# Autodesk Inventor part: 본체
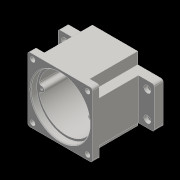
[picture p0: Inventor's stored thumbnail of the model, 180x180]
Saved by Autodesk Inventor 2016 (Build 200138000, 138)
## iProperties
Created: 2020-08
Part Number: 본체
Material: 일반
Document SubType Name: Modeling
Designer: User
Density: 1 g/cm^3
Appearance: 기본값
Author: User
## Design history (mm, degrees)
sketch "스케치1"
  geometry: L1 (47, 47)-(-47, 47); L2 (-47, 47)-(-47, -47); L3 (-47, -47)-(47, -47); L4 (47, -47)-(47, 47); L5 (47, 47)-(-47, -47); L6 (-47, 47)-(47, -47); 1 further point
  constraints: 12 end point, 2 midpoint, 2 parallel, 1 horizontal, 1 perpendicular
  dimensions: "d0" = 94 distance of L2.end L3.end; "d1" = 94 distance of L1.end L2.end
extrude "돌출1" new body sketch "스케치1" distance "d2" = 80; taper "d3" = 0 deg
sketch "스케치2"
  geometry: L1 (-70, -30)-(70, -30); L2 (70, -30)-(70, 30); L3 (70, 30)-(-70, 30); L4 (-70, 30)-(-70, -30); L5 (-70, -30)-(70, 30); L6 (70, -30)-(-70, 30); 1 further point
  constraints: 12 end point, 2 midpoint, 2 parallel, 1 horizontal, 1 perpendicular
  dimensions: "d4" = 60 distance of L1.end L2.end; "d5" = 140 distance of L2.end L3.end
extrude "돌출2" join sketch "스케치2" distance "d6" = 13; taper "d7" = 0 deg
sketch "스케치4"
  geometry: L1 (47, 47)-(-47, 47) reference; L2 (-47, 47)-(-33, 47); L3 (-33, 47)-(-33, 30); L4 (-33, 30)-(-47, 30); L5 (-47, 30)-(-47, 47); 1 further point
  constraints: 8 end point, 2 parallel, 1 horizontal, 1 perpendicular
  dimensions: "d8" = 17 distance of L2.end L3.end; "d9" = 14 distance of L3.end L4.end
extrude "돌출3" cut sketch "스케치4" distance "d10" = 70; taper "d11" = 0 deg
sketch "스케치5"
  geometry: L1 (-47, 47)-(-33, 47) reference; L2 (-47, 30)-(-47, 47) reference; C1 r 3.5 at (-40, 40); 1 further point
  constraints: 1 centre point
  dimensions: "d12" = 7 distance from line of L1 C1.centre; "d13" = 7 distance from line of C1.centre L2; "d14" = 7 diameter of C1
extrude "돌출4" cut sketch "스케치5" distance "d15" = 70; taper "d16" = 0 deg
sketch "스케치6"
  geometry: C1 r 27.5 at (0, 11); 1 further point
  constraints: 1 centre point, 1 vertical alignment
  dimensions: "d23" = 55 diameter of C1; "d24" = 11 distance of point (0, 0) C1.centre
extrude "돌출5" join sketch "스케치6" distance "d25" = 7; taper "d26" = 0 deg
sketch "스케치7"
  geometry: C1 r 27.5 at (0, 0) reference; C2 r 16 at (0, 0); 1 further point
  constraints: 1 centre point, 1 coincident
  dimensions: "d27" = 32 diameter of C2
extrude "돌출6" cut sketch "스케치7" distance "d28" = 8.3; taper "d29" = 0 deg
sketch "스케치8"
  geometry: C1 r 43 at (0, 0); 1 further point
  constraints: 1 centre point, 1 coincident
  dimensions: "d30" = 86 diameter of C1
extrude "돌출7" cut sketch "스케치8" distance "d31" = 9; taper "d32" = 0 deg
sketch "스케치9"
  geometry: C1 r 40 at (0, 0); 1 further point
  constraints: 1 centre point, 1 coincident
  dimensions: "d33" = 80 diameter of C1
extrude "돌출8" cut sketch "스케치9" distance "d34" = 62; taper "d35" = 0 deg
sketch "스케치10"
  geometry: C1 r 16 at (0, -11) reference; C2 r 21 at (0, -11); 1 further point
  constraints: 1 centre point, 1 coincident
  dimensions: "d36" = 42 diameter of C2
extrude "돌출9" join sketch "스케치10" distance "d37" = 7; taper "d38" = 0 deg
sketch "스케치11"
  geometry: L1 (-98, 0)-(98, 0) reference; L2 (0, -65.8)-(0, 65.8) reference; C1 r 15 at (0, 20); C2 r 21 at (0, -11) reference; 1 further point
  constraints: 1 centre point, 1 vertical alignment
  dimensions: "d39" = 20 distance from line of L1 C1.centre; "d40" = 30 diameter of C1
extrude "돌출10" join sketch "스케치11" distance "d41" = 7; taper "d42" = 0 deg
sketch "스케치15"
  geometry: L1 (-98, 0)-(98, 0) reference; L2 (0, -65.8)-(0, 65.8) reference; A1 r 4 centre (36, 0) between (36.19, 3.995) and (36.19, -3.995); A2 r 3 centre (36.333, -6.992) between (39.279, -7.559) and (36.19, -3.995); A3 r 3 centre (36.333, 6.992) between (36.19, 3.995) and (39.279, 7.559); A4 r 40 centre (0, 0) between (39.279, -7.559) and (39.279, 7.559) reference; 1 further point
  constraints: 8 point on circle, 5 tangent, 3 centre point, 1 horizontal alignment, 1 point on line
  dimensions: "d54" = 8 diameter of A1; "d55" = 6 diameter of A3; "d56" = 6 diameter of A2
extrude "돌출14" join sketch "스케치15" stored distance "d57" = 3; taper "d58" = 0 deg
sketch "스케치16"
  geometry: A1 r 4 centre (36, 0) between (36.19, 3.995) and (36.19, -3.995) reference; 2 further points
  constraints: 1 coincident
hole "구멍1" sketch "스케치16" at (36, 0) diameter "d59" = 3.242; stored, may be unused: countersink angle "d63" = 90 deg, drill point angle "d65" = 118 deg; dims "d60" = 7, "d61" = 4, "d62" = 2, "d64" = 9
sketch "스케치17"
  geometry: L1 (-98, 0)-(98, 0) reference; L2 (0, -65.8)-(0, 65.8) reference; L3 (47, -30)-(70, -30) reference; 3 further points
  dimensions: "d66" = 38 distance of point (60, 19) point (60, -19); "d67" = 60 distance from line of point (60, -19) L2; "d68" = 60 distance from line of L2 point (60, 19); "d69" = 11 distance from line of point (60, -19) L3
hole "구멍2" sketch "스케치17" at (60, -19), (60, 19) diameter "d70" = 4.5; stored, may be unused: countersink angle "d74" = 90 deg, drill point angle "d76" = 118 deg; dims "d71" = 7, "d72" = 10, "d73" = 5, "d75" = 20
chamfer "모따기1" distance "d77" = 0.8; stored, may be unused: second distance "d78" = 2, angle "d79" = 30 deg
fillet "모깎기1" dims "d83" = 3
chamfer "모따기5" distance "d91" = 1; stored, may be unused: second distance "d92" = 2, angle "d93" = 30 deg
sketch "스케치18"
  geometry: L1 (-77, -10)-(11, -10) reference; L2 (14, 57)-(14, 0) reference; 2 further points
  constraints: 1 other
  dimensions: "d94" = 40 distance from line of L1 point (-33, 30); "d95" = 47 distance from line of L2 point (-33, 30)
feature "엠보싱1" sketch "스케치18" dims "d96" = 0.5, "d97" = 0
sketch "스케치19"
  geometry: C1 r 17.5 at (0, -11); A1 r 21 centre (0, -11) between (-8.978, 7.984) and (8.978, 7.984) reference; A2 r 15 centre (0, 20) between (8.978, 7.984) and (-8.978, 7.984) reference; 1 further point
  constraints: 1 centre point, 1 coincident
  dimensions: "d98" = 35 diameter of C1
extrude "돌출15" cut sketch "스케치19" distance "d99" = 10; taper "d100" = 0 deg
sketch "스케치20"
  geometry: C1 r 17.5 at (0, 0) reference; C2 r 12.5 at (0, 0); 1 further point
  constraints: 1 centre point, 1 coincident
  dimensions: "d101" = 25 diameter of C2
extrude "돌출16" cut sketch "스케치20" distance "d102" = 10; taper "d103" = 0 deg
sketch "스케치21"
  geometry: C1 r 11 at (0, 20); A1 r 15 centre (0, 20) between (8.978, 7.984) and (-8.978, 7.984) reference; 1 further point
  constraints: 1 centre point, 1 coincident
  dimensions: "d104" = 22 diameter of C1
extrude "돌출17" cut sketch "스케치21" distance "d105" = 7; taper "d106" = 0 deg
sketch "스케치22"
  geometry: C1 r 11 at (0, 0) reference; C2 r 9.5 at (0, 0); 1 further point
  constraints: 1 centre point, 1 coincident
  dimensions: "d107" = 19 diameter of C2
extrude "돌출18" cut sketch "스케치22" distance "d108" = 3; taper "d109" = 0 deg
chamfer "모따기6" distance "d110" = 1; stored, may be unused: second distance "d111" = 2, angle "d112" = 30 deg
fillet "모깎기3" dims "d113" = 3
node "솔리드1"
mirror "대칭1"
mirror "대칭2"
pattern_linear "직사각형 패턴1" dims "d19" = 80
mirror "대칭3"
mirror "대칭4"
